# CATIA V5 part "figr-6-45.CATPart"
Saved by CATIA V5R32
Part number: Part1
Bounding box of the stored display mesh (mm): x -26.811 to 26.811, y -47.298 to 47.298, z 0 to 31.431
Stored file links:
  D:\PROJECTS\Project 2022\CATIA V5 6R 2022\Resources\Part Files\c06_catia_v5_6r2022_prt\figr-6-45.CATPart
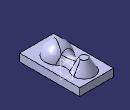
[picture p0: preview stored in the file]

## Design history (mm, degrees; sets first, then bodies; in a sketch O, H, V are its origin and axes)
Body1 (main body)
  Sketch1 on xy-plane, origin (0, 0, 0), H (1, 0, 0), V (0, 1, 0)
    line L1 (-26.8114, 47.2981) -> (26.8114, 47.2981)
    line L2 (26.8114, 47.2981) -> (26.8114, -47.2981)
    line L3 (26.8114, -47.2981) -> (-26.8114, -47.2981)
    line L4 (-26.8114, -47.2981) -> (-26.8114, 47.2981)
    axis line L5 (26.8114, -47.2981) -> (-26.8114, 47.2981)
    horizontal: L1 H, L3 H
    vertical: L2 V, L4 V
    coincidence: L5 O
    midpoint: L5 O
  Pad1: profile Sketch1, direction (0, 0, 1), length 12
  Sketch2 on yz-plane, origin (0, 0, 0), H (0, 1, 0), V (0, 0, 1)
    axis line L1 (-14.846, 35.4307) -> (-14.846, -5.9324)
    arc A1 centre (-14.846, 12.2093) radius 19.2216 from (-14.846, 31.431) to (-33.1926, 6.476) ccw
    point P3 (-14.846, 12.2093)
    point P4 (-14.846, 31.431)
    line L2 (-14.846, 31.431) -> (-14.846, 8.3996)
    line L3 (-14.846, 8.3996) -> (-33.1926, 6.476)
    vertical: L1 V, L2 V
    coincidence: P3 L1, P4 L1, A1 O
  Shaft1: profile Sketch2, axis Sketch2.L1, angle 360
  Sketch3 on face of Pad1, origin (0, 0, 12), H (1, 0, 0), V (0, 1, 0)
    circle A1 centre (0, 27.4246) radius 16.1543
    point P1 (0, 27.4246)
    coincidence: P1 V
  Pad2: profile Sketch3, direction (0, 0, 1), length 18
  Draft1: Angle 30, Neutral face of Pad1, PullDir face of Pad1, SupportToDraft face of Pad2
  FaceFillet1: Face1 face of Shaft1, Face2 face of Pad2, Radius 15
